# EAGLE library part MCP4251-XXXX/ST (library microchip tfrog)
MCP4251 7/8-Bit Dual SPI Digital Potentiometer with Volatile Memory Doc: http://www.microchip.com/wwwproducts/Devices.aspx?dDocName=en531890 Ref Used: MCP4251-104E/ST (8 bits, 100K ohms)
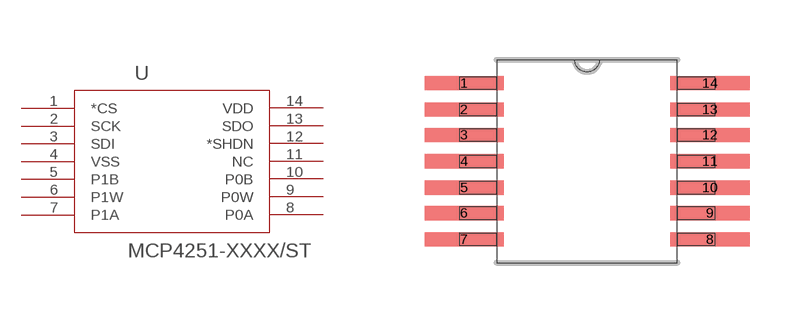
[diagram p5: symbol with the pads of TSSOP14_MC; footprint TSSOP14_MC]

Designator prefix -

## MCP4251-XXXX/ST  [TSSOP14_MC]
1  *CS  pas
2  SCK  pas
3  SDI  pas
4  VSS  pas
5  P1B  pas
6  P1W  pas
7  P1A  pas
8  P0A  pas
9  P0W  pas
10  P0B  pas
11  NC  pas
12  *SHDN  pas
13  SDO  pas
14  VDD  pas

## Footprint TSSOP14_MC (pad centres in mm)
TSOP14 with long pads (0.078inch instead of 0.058)
smd 1.981 x 0.356: 1 -3.073,1.956; 2 -3.073,1.295; 3 -3.073,0.66; 4 -3.073,0; 5 -3.073,-0.66; 6 -3.073,-1.295; 7 -3.073,-1.956; 8 3.073,-1.956; 9 3.073,-1.295; 10 3.073,-0.66; 11 3.073,0; 12 3.073,0.66; 13 3.073,1.295; 14 3.073,1.956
